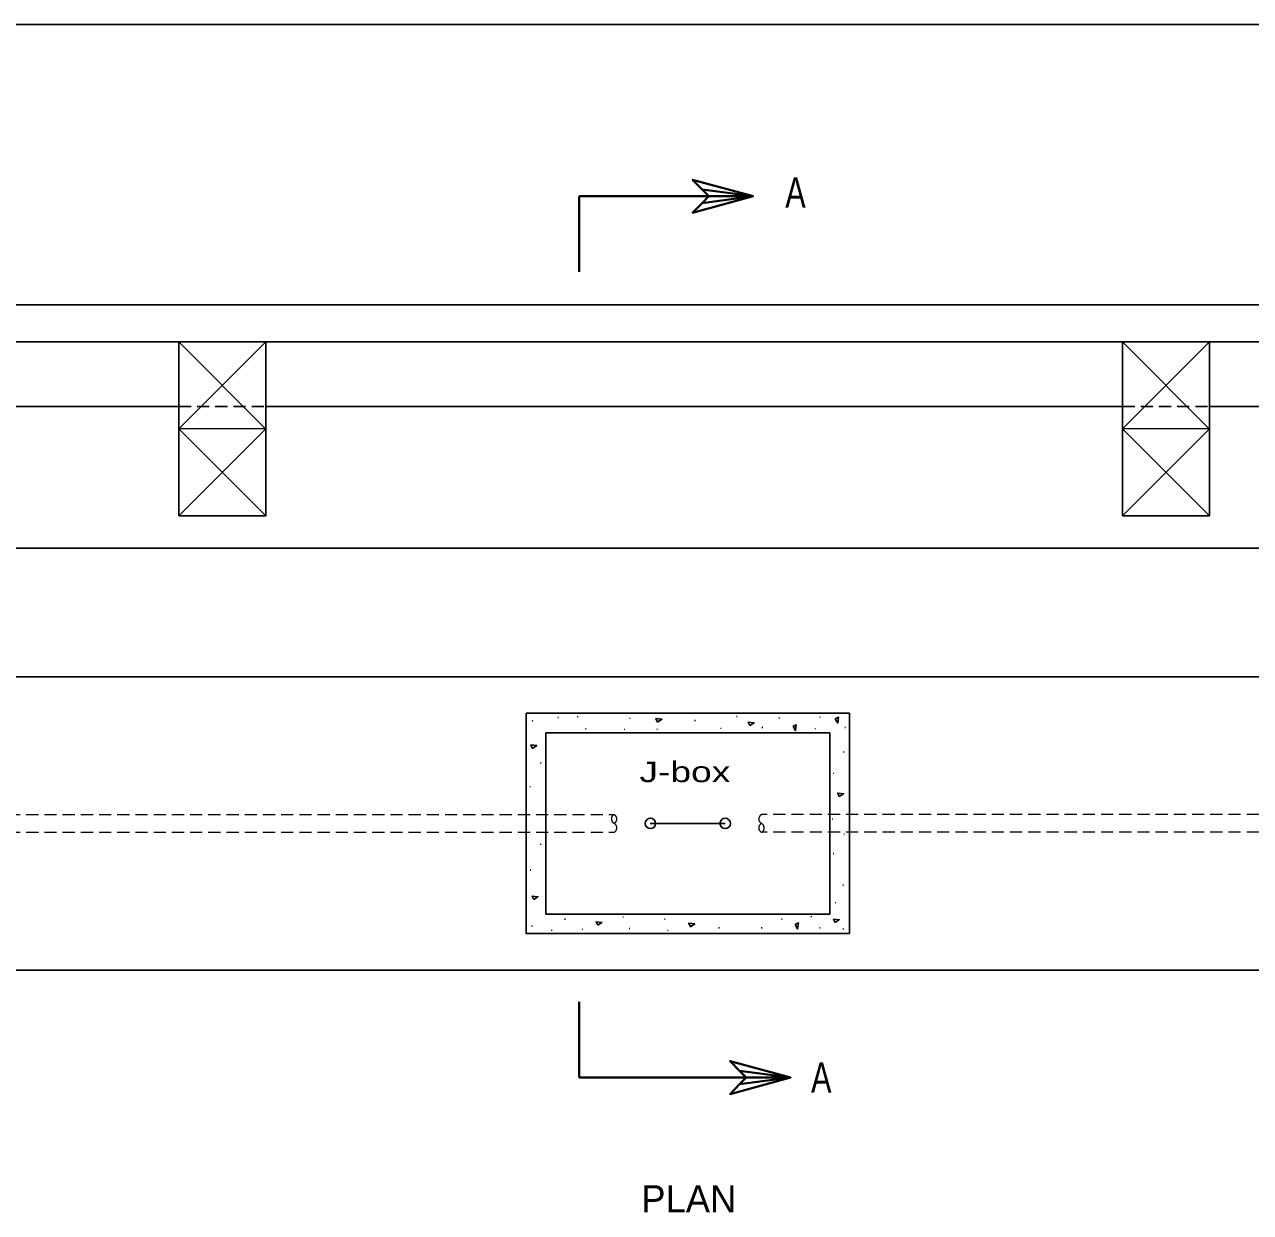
# Model space of a CAD drawing. Extents: x 993470 to 994006, y 1010815 to 1011161.
# Drawn here: x 993630.6 to 993791.1, y 1011005.9 to 1011161.5 of the extents above; entities that cross this region are included whole.
import ezdxf
from ezdxf.enums import TextEntityAlignment as Align

# ---------------------------------------------------------------- set-up
doc = ezdxf.new("R2010")
doc.units = 0
doc.header["$LTSCALE"] = 0.53
doc.linetypes.add('LONG_DASHED', pattern=[7.5, 6, -1.5])
doc.linetypes.add('MEDIUM_DASHED', pattern=[4.5, 3, -1.5])
for name, color, linetype, lineweight in [('1', 7, 'Continuous', 25), ('16', 7, 'Continuous', 25), ('20', 7, 'Continuous', 13), ('3', 7, 'Continuous', 25), ('30', 7, 'Continuous', 25), ('32', 7, 'Continuous', 25)]:
    doc.layers.add(name, color=color, linetype=linetype, lineweight=lineweight)

msp = doc.modelspace()

# ---------------------------------------------------------------- linework, layer by layer
at = {"layer": '1'}
for p, q in [((993650.777, 1011119.934), (993650.777, 1011097.116)), ((993662.179, 1011119.934), (993662.179, 1011097.116)), ((993774.381, 1011119.934), (993774.381, 1011097.116)), ((993785.783, 1011119.934), (993785.783, 1011097.116)), ((993509.149, 1011076.054), (993918.64, 1011076.054)), ((993712.53, 1011056.854), (993722.348, 1011056.854))]:
    msp.add_line(p, q, dxfattribs=at)
at = {"layer": '1', "linetype": 'MEDIUM_DASHED', "lineweight": 13}
for p, q in [((993509.149, 1011058.023), (993707.785, 1011058.023)), ((993918.64, 1011058.023), (993727.094, 1011058.023)), ((993509.149, 1011055.697), (993707.785, 1011055.697)), ((993918.64, 1011055.697), (993727.094, 1011055.697))]:
    msp.add_line(p, q, dxfattribs=at)
at = {"layer": '1'}
for centre in [(993712.5373, 1011056.8606), (993722.3406, 1011056.8606)]:
    msp.add_circle(centre, 0.6879, dxfattribs=at)
at = {"layer": '1', "linetype": 'MEDIUM_DASHED', "lineweight": 13}
for centre, start, end in [((993708.0749, 1011057.446), 116.62161, 243.37839), ((993707.4955, 1011057.4317), 296.62161, 63.37839), ((993727.3829, 1011057.4317), 116.62161, 243.37839), ((993707.4955, 1011056.2759), 296.62161, 63.37839), ((993727.3829, 1011056.2759), 116.62161, 243.37839), ((993726.8036, 1011056.2616), 296.62161, 63.37839)]:
    msp.add_arc(centre, 0.6465, start, end, dxfattribs=at)
at = {"layer": '16', "lineweight": 40}
for points in [[(993719.315, 1011139.854), (993718.073, 1011141.14), (993725.993, 1011138.984), (993718.073, 1011136.816), (993719.315, 1011138.1), (993725.993, 1011138.984), (993719.315, 1011139.854), (993720.185, 1011138.984), (993719.315, 1011138.1)], [(993724.225, 1011024.444), (993722.983, 1011025.728), (993730.903, 1011023.574), (993722.983, 1011021.406), (993724.225, 1011022.69), (993730.903, 1011023.574), (993724.225, 1011024.444), (993725.095, 1011023.574), (993724.225, 1011022.69)]]:
    msp.add_lwpolyline(points, dxfattribs=at)
at = {"layer": '3'}
for p, q in [((993738.63, 1011071.287), (993696.262, 1011071.287)), ((993738.63, 1011042.421), (993738.63, 1011071.287)), ((993736.046, 1011068.719), (993698.832, 1011068.719)), ((993698.832, 1011044.989), (993698.832, 1011068.719)), ((993736.046, 1011044.989), (993736.046, 1011068.719)), ((993736.046, 1011044.989), (993698.832, 1011044.989))]:
    msp.add_line(p, q, dxfattribs=at)
msp.add_lwpolyline([(993738.63, 1011042.421), (993696.262, 1011042.421), (993696.262, 1011071.287)], dxfattribs=at)
for points in [[(993713.472, 1011070.131), (993713.272, 1011070.589), (993714.042, 1011070.503)], [(993736.76, 1011070.531), (993737.188, 1011070.759), (993737.088, 1011069.989)], [(993725.572, 1011069.675), (993725.358, 1011070.131), (993726.13, 1011070.017)], [(993731.224, 1011069.575), (993731.652, 1011069.761), (993731.538, 1011069.019)], [(993697.104, 1011066.679), (993696.89, 1011067.135), (993697.662, 1011067.049)], [(993737.274, 1011060.371), (993737.074, 1011060.829), (993737.844, 1011060.743)], [(993697.262, 1011046.887), (993697.034, 1011047.329), (993697.804, 1011047.243)], [(993705.652, 1011043.533), (993705.424, 1011043.975), (993706.194, 1011043.889)], [(993717.782, 1011043.333), (993717.568, 1011043.789), (993718.338, 1011043.705)], [(993731.48, 1011043.619), (993731.952, 1011043.819), (993731.822, 1011043.047)], [(993736.732, 1011043.875), (993736.504, 1011044.317), (993737.274, 1011044.233)]]:
    msp.add_lwpolyline(points, close=True, dxfattribs=at)
at = {"layer": '30'}
msp.add_line((994005.609, 1011161.474), (993469.979, 1011161.474), dxfattribs=at)
at = {"layer": '32', "lineweight": 40}
for p, q in [((993703.219, 1011138.984), (993725.993, 1011138.984)), ((993703.219, 1011138.984), (993703.219, 1011129.082)), ((993703.219, 1011023.574), (993703.219, 1011033.494)), ((993703.219, 1011023.574), (993730.903, 1011023.574))]:
    msp.add_line(p, q, dxfattribs=at)
at = {"layer": '32'}
for p, q in [((993509.149, 1011124.772), (993918.64, 1011124.772)), ((993509.149, 1011119.934), (993918.64, 1011119.934)), ((993538.559, 1011111.458), (993650.777, 1011111.458)), ((993662.179, 1011111.458), (993774.381, 1011111.458)), ((993785.783, 1011111.458), (993897.987, 1011111.458)), ((993662.179, 1011097.116), (993650.777, 1011097.116)), ((993785.783, 1011097.116), (993774.381, 1011097.116)), ((993509.149, 1011092.92), (993918.64, 1011092.92)), ((993509.149, 1011037.654), (993918.64, 1011037.654))]:
    msp.add_line(p, q, dxfattribs=at)
at = {"layer": '32', "linetype": 'LONG_DASHED', "lineweight": 13}
for p, q in [((993662.179, 1011119.934), (993650.777, 1011119.934)), ((993785.783, 1011119.934), (993774.381, 1011119.934))]:
    msp.add_line(p, q, dxfattribs=at)
at = {"layer": '32', "lineweight": 13}
for p, q in [((993650.777, 1011119.934), (993662.179, 1011108.504)), ((993650.791, 1011108.532), (993662.179, 1011119.934)), ((993774.381, 1011119.934), (993785.783, 1011108.504)), ((993774.395, 1011108.532), (993785.783, 1011119.934)), ((993662.165, 1011108.532), (993650.777, 1011108.546)), ((993650.777, 1011108.546), (993662.179, 1011097.116)), ((993650.777, 1011097.116), (993662.165, 1011108.532)), ((993785.769, 1011108.532), (993774.381, 1011108.546)), ((993774.381, 1011108.546), (993785.783, 1011097.116)), ((993774.381, 1011097.116), (993785.769, 1011108.532))]:
    msp.add_line(p, q, dxfattribs=at)
at = {"layer": '32', "linetype": 'MEDIUM_DASHED'}
for p, q in [((993650.777, 1011111.458), (993662.179, 1011111.458)), ((993774.381, 1011111.458), (993785.783, 1011111.458))]:
    msp.add_line(p, q, dxfattribs=at)

# ---------------------------------------------------------------- texts
at = {"layer": '20', "width": 0.75}
for p in [(993730.203, 1011137.486), (993733.584, 1011021.588)]:
    msp.add_text('A', height=3.996, dxfattribs=at).set_placement(p)
at = {"layer": '20', "width": 1.35}
msp.add_text('J-box', height=2.697, dxfattribs=at).set_placement((993717.055, 1011062.26), align=Align.CENTER)
at = {"layer": '20'}
msp.add_text('PLAN', height=3.567, dxfattribs=at).set_placement((993717.568, 1011005.908), align=Align.CENTER)
at = {"layer": '3'}
for p in [(993700.4644, 1011070.817), (993703.0044, 1011070.931), (993709.8544, 1011070.703), (993723.8664, 1011070.945), (993729.4324, 1011070.759), (993734.7404, 1011070.845), (993697.0964, 1011070.389), (993704.0744, 1011069.333), (993709.1404, 1011069.275), (993713.4224, 1011069.275), (993718.3724, 1011070.431), (993721.7544, 1011069.405), (993727.2064, 1011069.505), (993734.1264, 1011069.361), (993738.0504, 1011069.505), (993737.8524, 1011066.307), (993698.1664, 1011064.853), (993736.5244, 1011063.497), (993696.7824, 1011061.769), (993736.3964, 1011057.517), (993737.9084, 1011055.549), (993698.1664, 1011054.207), (993736.5244, 1011053.009), (993696.8404, 1011050.825), (993737.7944, 1011048.869), (993736.7804, 1011046.587), (993697.0404, 1011043.505), (993701.3484, 1011044.417), (993708.9704, 1011044.703), (993709.8104, 1011043.191), (993714.4344, 1011044.417), (993721.5264, 1011043.277), (993727.1064, 1011043.277), (993729.7604, 1011044.417), (993733.6124, 1011044.731), (993734.7404, 1011043.277), (993699.6084, 1011042.947), (993703.6464, 1011043.077), (993714.8204, 1011042.947), (993737.8084, 1011043.133)]:
    msp.add_text('.', height=1.203, rotation=180, dxfattribs=at).set_placement(p, align=Align.CENTER)

doc.saveas('drawing.dxf')
